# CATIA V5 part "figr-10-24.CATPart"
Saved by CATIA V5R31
Part number: Part1
Bounding box of the stored display mesh (mm): x -180.516 to 0, y -36.805 to 65.824, z 0 to 36.805
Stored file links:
  D:\PROJECTS\Project 2021\US EDITION\CATIA V5 6R 2021\Resources\Part Files\c10_catia_v5_6r2021_prt\c10_catia_v5_6r2021_prt\figr-10-24.CATPart
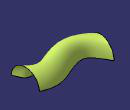
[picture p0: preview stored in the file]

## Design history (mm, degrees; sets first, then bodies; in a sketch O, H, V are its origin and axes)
Set1
  Sweep1: type Unspec, Profile Sketch2, Guide Sketch1
Body1 (main body)
  Sketch1 on xy-plane, origin (0, 0, 0), H (1, 0, 0), V (0, 1, 0)
    spline S1 through (0, 0) (-31.5913, 14.7273) (-94.8038, 0) (-174.5181, 29.5113)
    point P1 (0, 0)
    point P2 (-94.8038, 0)
    coincidence: P1 O, P2 H
  Sketch2 on yz-plane, origin (0, 0, 0), H (0, 1, 0), V (0, 0, 1)
    arc A1 centre (0, 0) radius 36.8048 from (36.8048, 0) to (-36.8048, 0) ccw
    point P1 (-36.8048, 0)
    point P2 (36.8048, 0)
    coincidence: P1 H, P2 H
